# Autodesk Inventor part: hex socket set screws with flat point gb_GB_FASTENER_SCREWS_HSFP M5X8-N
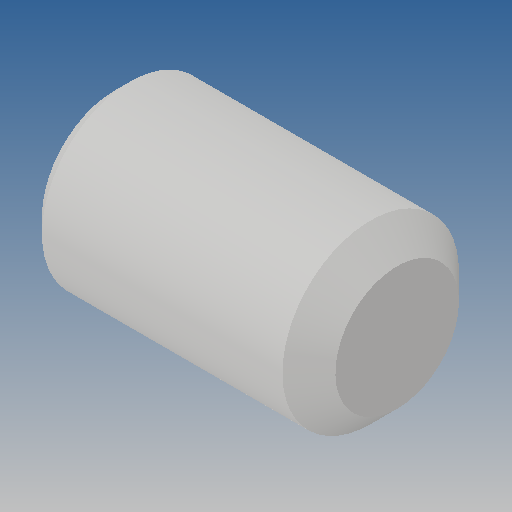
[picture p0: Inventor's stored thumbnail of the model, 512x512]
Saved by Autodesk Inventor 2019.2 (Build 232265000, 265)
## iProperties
Created: 2013-04
Part Number: hex socket set screws with flat point gb_GB_FASTENER_SCREWS_HSFP M5X8-N
Material: Ogólny
Document SubType Name: Modeling
Designer: CADENGINEERING4
Density: 1 g/cm^3
Appearance: Domyślna
Author: CADENGINEERING4
Revision Number: ÈÎºÎ
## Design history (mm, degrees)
feature "Cut-Revolve1"
node "Bryła1"
